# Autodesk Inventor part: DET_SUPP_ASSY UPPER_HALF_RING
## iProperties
Shininess: 64.0
Length Units: 11272
Angle Units: 11279
Time Units: 11290
Mass Units: 11286
Length Display Precision: 3
Angle Display Precision: 2
Compacted: True
Part Number: DET_SUPP_ASSY UPPER_HALF_RING
Document SubType Name: Modeling
Created: 2004-08
Designer: John Blackburn
Manufacturer: Standard
Standards Organization: Custom
Material: Aluminum-6061
Density: 0.0
Volumn: 0.0
Area: 0.0
PropertySet Name: Model Information
Control State: 0
Master: False
Checked Out: False
Author: John Blackburn
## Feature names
1. ExtrusionBlind1
2. AM_HOLE_SI0029_1 [Hole]
3. AM_HOLE_SI0029_2 [Hole]
4. Polar Pattern1 [Circular Pattern]
